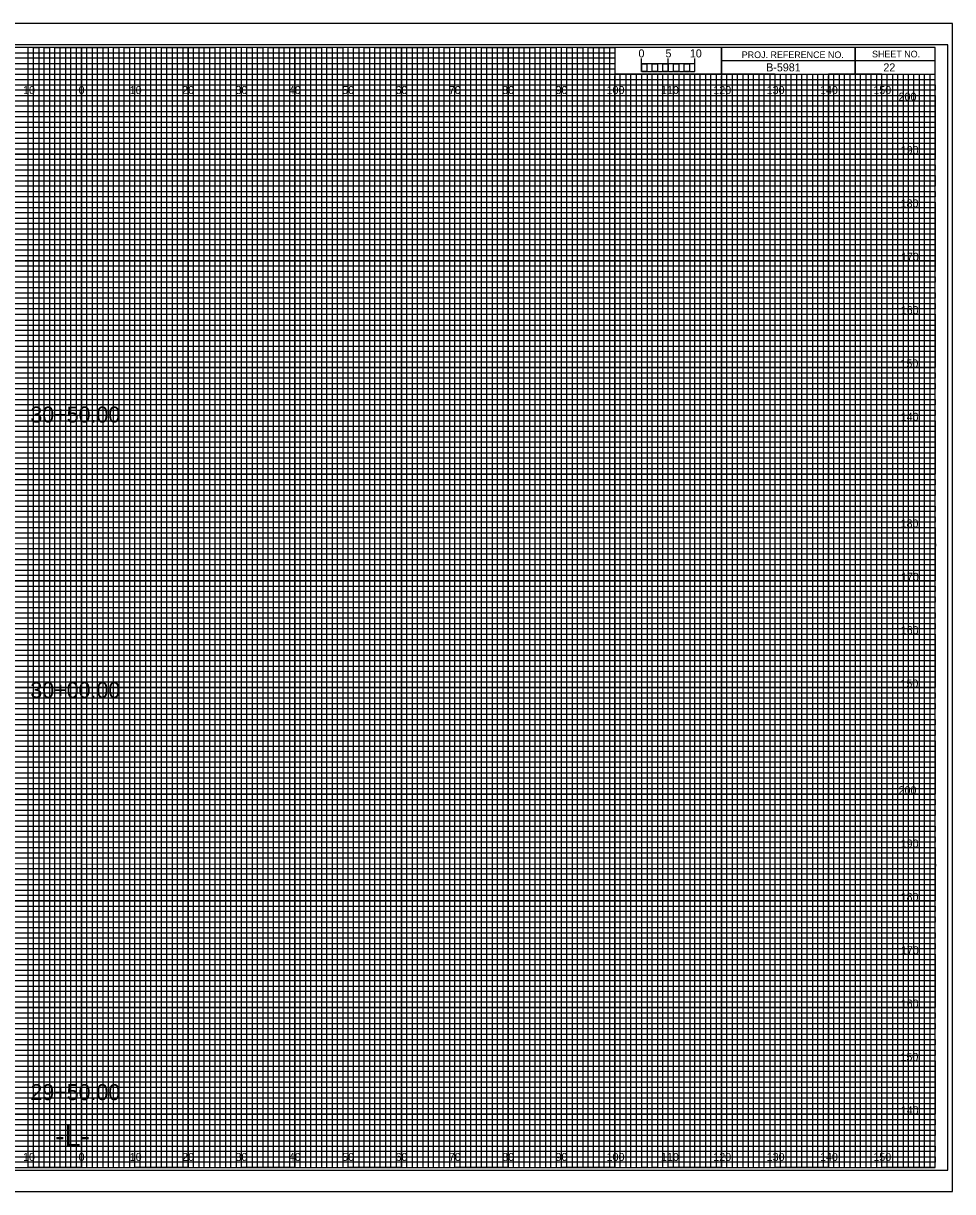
# Model space of a CAD drawing. Extents: x -13 to 323, y -5 to 4174.
# Drawn here: x 149.1 to 323.3, y 3515.5 to 3734.5 of the extents above; entities that cross this region are included whole.
import ezdxf

# ---------------------------------------------------------------- set-up
doc = ezdxf.new("R2010")
doc.units = 0
for name, color, linetype in [('Exist Cross Section Cell', 7, 'Continuous'), ('Exist XS Center Line Elevation Label', 7, 'Continuous'), ('Exist XS Ground Line', 7, 'Continuous'), ('Prop CMT Concrete Structures', 7, 'Continuous'), ('Prop CMT Guardrail Graphics', 7, 'Continuous'), ('Prop CMT Pvmt Course 1', 7, 'Continuous'), ('Prop CMT Pvmt Course 2', 7, 'Continuous'), ('Prop CMT Pvmt Course 3', 7, 'Continuous'), ('Prop CMT Pvmt Surface', 7, 'Continuous'), ('Prop CMT Shld Paved Course 1', 7, 'Continuous'), ('Prop CMT Shld Paved Course 2', 7, 'Continuous'), ('Prop CMT Shld Paved Course 3', 7, 'Continuous'), ('Prop CMT Subgrade Earthwork', 7, 'Continuous'), ('Prop XS Ditch Standard Text', 7, 'Continuous'), ('Prop XS SE Text', 7, 'Continuous'), ('Prop XS Side Slope Text', 7, 'Continuous'), ('Scratch_Level_0', 7, 'Continuous')]:
    doc.layers.add(name, color=color, linetype=linetype)

msp = doc.modelspace()

# ---------------------------------------------------------------- linework, layer by layer
at = {"layer": 'Exist XS Center Line Elevation Label'}
for points in [[(145, 3520), (155, 3520), (155, 3730), (165, 3730), (165, 3520), (175, 3520), (175, 3730), (185, 3730), (185, 3520), (195, 3520), (195, 3730), (205, 3730), (205, 3520), (215, 3520), (215, 3730), (225, 3730), (225, 3520), (235, 3520), (235, 3730), (245, 3730), (245, 3520), (255, 3520), (255, 3730), (259.93, 3730), (260, 3730), (260, 3725), (264.99, 3725), (264.99, 3520), (275, 3520), (275, 3725), (285, 3725), (285, 3520), (295, 3520), (295, 3725), (305, 3725), (305, 3520), (315, 3520), (315, 3725)], [(0, 3725), (275, 3725)], [(0, 3705), (320, 3705), (320, 3715), (0, 3715)], [(0, 3685), (320, 3685), (320, 3695), (0, 3695)], [(0, 3665), (320, 3665), (320, 3675), (0, 3675)], [(0, 3645), (320, 3645), (320, 3655), (0, 3655)], [(0, 3625), (320, 3625), (320, 3635), (0, 3635)], [(0, 3605), (320, 3605), (320, 3615), (0, 3615)], [(0, 3585), (320, 3585), (320, 3595), (0, 3595)], [(0, 3565), (320, 3565), (320, 3575), (0, 3575)], [(0, 3545), (320, 3545), (320, 3555), (0, 3555)], [(0, 3525), (320, 3525), (320, 3535), (0, 3535)]]:
    msp.add_lwpolyline(points, dxfattribs=at)
at = {"layer": 'Exist XS Ground Line'}
for p, q in [((150, 3730), (140, 3730)), ((150, 3520), (150, 3730)), ((170, 3730), (160, 3730)), ((160, 3730), (160, 3520)), ((170, 3520), (170, 3730)), ((190, 3730), (180, 3730)), ((180, 3730), (180, 3520)), ((190, 3520), (190, 3730)), ((210, 3730), (200, 3730)), ((200, 3730), (200, 3520)), ((210, 3520), (210, 3730)), ((230, 3730), (220, 3730)), ((220, 3730), (220, 3520)), ((230, 3520), (230, 3730)), ((250, 3730), (240, 3730)), ((240, 3730), (240, 3520)), ((250, 3520), (250, 3730)), ((260, 3730), (260, 3520)), ((270, 3520), (270, 3725)), ((290, 3725), (280, 3725)), ((280, 3725), (280, 3520)), ((290, 3520), (290, 3725)), ((310, 3725), (300, 3725)), ((300, 3725), (300, 3520)), ((310, 3520), (310, 3725)), ((160, 3520), (150, 3520)), ((180, 3520), (170, 3520)), ((200, 3520), (190, 3520)), ((220, 3520), (210, 3520)), ((240, 3520), (230, 3520)), ((260, 3520), (250, 3520)), ((280, 3520), (270, 3520)), ((300, 3520), (290, 3520)), ((320, 3520), (310, 3520)), ((320, 3520), (320, 3520))]:
    msp.add_line(p, q, dxfattribs=at)
for points in [[(0, 3720), (320, 3720), (320, 3710), (0, 3710)], [(0, 3700), (320, 3700), (320, 3690), (0, 3690)], [(0, 3680), (320, 3680), (320, 3670), (0, 3670)], [(0, 3660), (320, 3660), (320, 3650), (0, 3650)], [(0, 3640), (320, 3640), (320, 3630), (0, 3630)], [(0, 3620), (320, 3620), (320, 3610), (0, 3610)], [(0, 3600), (320, 3600), (320, 3590), (0, 3590)], [(0, 3580), (320, 3580), (320, 3570), (0, 3570)], [(0, 3560), (320, 3560), (320, 3550), (0, 3550)], [(0, 3540), (320, 3540), (320, 3530), (0, 3530)]]:
    msp.add_lwpolyline(points, dxfattribs=at)
at = {"layer": 'Prop CMT Pvmt Course 1'}
for p, q in [((323.3, 3734.5), (-13.4, 3734.5)), ((-13.4, 3515.5), (323.3, 3515.5))]:
    msp.add_line(p, q, dxfattribs=at)
at = {"layer": 'Prop CMT Pvmt Course 2'}
msp.add_lwpolyline([(-13.4, 3515.5), (323.3, 3515.5), (323.3, 3734.5), (-13.4, 3734.5)], close=True, dxfattribs=at)
at = {"layer": 'Prop CMT Pvmt Course 3'}
msp.add_lwpolyline([(-10.8, 3519.5), (322.4, 3519.5), (322.4, 3730.5), (-10.8, 3730.5)], close=True, dxfattribs=at)
at = {"layer": 'Prop CMT Shld Paved Course 1'}
for p, q in [((305, 3730), (305, 3725)), ((305, 3725), (305, 3730)), ((280, 3727.5), (280, 3725)), ((320, 3727.49), (280, 3727.49)), ((280, 3725), (320, 3725))]:
    msp.add_line(p, q, dxfattribs=at)
for points in [[(320, 3730), (0, 3730), (0, 3520), (320, 3520)], [(280, 3730), (260, 3730), (260, 3725.03), (280, 3725.03)], [(320, 3730), (280, 3730), (280, 3725), (320, 3725)]]:
    msp.add_lwpolyline(points, close=True, dxfattribs=at)
at = {"layer": 'Prop CMT Shld Paved Course 2'}
for p, q in [((267, 3725), (266.01, 3725)), ((266.01, 3725), (266.01, 3520)), ((267, 3520), (267, 3725)), ((269, 3725), (268, 3725)), ((268, 3725), (268, 3520)), ((269, 3520), (269, 3725)), ((266.01, 3520), (265, 3520)), ((268, 3520), (267, 3520))]:
    msp.add_line(p, q, dxfattribs=at)
for points in [[(150, 3520), (151, 3520), (151, 3730), (152, 3730), (152, 3520)], [(152, 3520), (153, 3520), (153, 3730), (154, 3730), (154, 3520)], [(155, 3520), (156, 3520), (156, 3730), (157, 3730), (157, 3520)], [(157, 3520), (158, 3520), (158, 3730), (159, 3730), (159, 3520)], [(160, 3520), (161, 3520), (161, 3730), (162, 3730), (162, 3520)], [(162, 3520), (163, 3520), (163, 3730), (164, 3730), (164, 3520)], [(165, 3520), (166, 3520), (166, 3730), (167, 3730), (167, 3520)], [(167, 3520), (168, 3520), (168, 3730), (169, 3730), (169, 3520)], [(170, 3520), (171, 3520), (171, 3730), (172, 3730), (172, 3520)], [(172, 3520), (173, 3520), (173, 3730), (174, 3730), (174, 3520)], [(175, 3520), (176, 3520), (176, 3730), (177, 3730), (177, 3520)], [(177, 3520), (178, 3520), (178, 3730), (179, 3730), (179, 3520)], [(180, 3520), (181, 3520), (181, 3730), (182, 3730), (182, 3520)], [(182, 3520), (183, 3520), (183, 3730), (184, 3730), (184, 3520)], [(185, 3520), (186, 3520), (186, 3730), (187, 3730), (187, 3520)], [(187, 3520), (188, 3520), (188, 3730), (189, 3730), (189, 3520)], [(190, 3520), (191, 3520), (191, 3730), (192, 3730), (192, 3520)], [(192, 3520), (193, 3520), (193, 3730), (194, 3730), (194, 3520)], [(195, 3520), (196, 3520), (196, 3730), (197, 3730), (197, 3520)], [(197, 3520), (198, 3520), (198, 3730), (199, 3730), (199, 3520)], [(200, 3520), (201, 3520), (201, 3730), (202, 3730), (202, 3520)], [(202, 3520), (203, 3520), (203, 3730), (204, 3730), (204, 3520)], [(205, 3520), (206, 3520), (206, 3730), (207, 3730), (207, 3520)], [(207, 3520), (208, 3520), (208, 3730), (209, 3730), (209, 3520)], [(210, 3520), (211, 3520), (211, 3730), (212, 3730), (212, 3520)], [(212, 3520), (213, 3520), (213, 3730), (214, 3730), (214, 3520)], [(215, 3520), (216, 3520), (216, 3730), (217, 3730), (217, 3520)], [(217, 3520), (218, 3520), (218, 3730), (219, 3730), (219, 3520)], [(220, 3520), (221, 3520), (221, 3730), (222, 3730), (222, 3520)], [(222, 3520), (223, 3520), (223, 3730), (224, 3730), (224, 3520)], [(225, 3520), (226, 3520), (226, 3730), (227, 3730), (227, 3520)], [(227, 3520), (228, 3520), (228, 3730), (229, 3730), (229, 3520)], [(230, 3520), (231, 3520), (231, 3730), (232, 3730), (232, 3520)], [(232, 3520), (233, 3520), (233, 3730), (234, 3730), (234, 3520)], [(235, 3520), (236, 3520), (236, 3730), (237, 3730), (237, 3520)], [(237, 3520), (238, 3520), (238, 3730), (239, 3730), (239, 3520)], [(240, 3520), (241, 3520), (241, 3730), (242, 3730), (242, 3520)], [(242, 3520), (243, 3520), (243, 3730), (244, 3730), (244, 3520)], [(245, 3520), (246, 3520), (246, 3730), (247, 3730), (247, 3520)], [(247, 3520), (248, 3520), (248, 3730), (249, 3730), (249, 3520)], [(250, 3520), (251, 3520), (251, 3730), (252, 3730), (252, 3520)], [(252, 3520), (253, 3520), (253, 3730), (254, 3730), (254, 3520)], [(255, 3520), (256, 3520), (256, 3730), (257, 3730), (257, 3520)], [(257, 3520), (258, 3520), (258, 3730), (259, 3730), (259, 3520)], [(260, 3520), (261, 3520), (261, 3725), (262.02, 3725), (262.02, 3520)], [(262, 3520), (263, 3520), (263, 3725), (263.99, 3725), (263.99, 3520)], [(270, 3520), (270.98, 3520), (270.98, 3725), (272, 3725), (272, 3520)], [(272, 3520), (273, 3520), (273, 3725), (274.05, 3725), (274.05, 3520)], [(275, 3520), (276, 3520), (276, 3725), (277, 3725), (277, 3520)], [(277, 3520), (278, 3520), (278, 3725), (279, 3725), (279, 3520)], [(280, 3520), (281, 3520), (281, 3725), (282, 3725), (282, 3520)], [(282, 3520), (283, 3520), (283, 3725), (284, 3725), (284, 3520)], [(285, 3520), (286, 3520), (286, 3725), (287, 3725), (287, 3520)], [(287, 3520), (288, 3520), (288, 3725), (289, 3725), (289, 3520)], [(290, 3520), (291, 3520), (291, 3725), (292, 3725), (292, 3520)], [(292, 3520), (293, 3520), (293, 3725), (294, 3725), (294, 3520)], [(295, 3520), (296, 3520), (296, 3725), (297, 3725), (297, 3520)], [(297, 3520), (298, 3520), (298, 3725), (299, 3725), (299, 3520)], [(300, 3520), (301, 3520), (301, 3725), (302, 3725), (302, 3520)], [(302, 3520), (303, 3520), (303, 3725), (304, 3725), (304, 3520)], [(305, 3520), (306, 3520), (306, 3725), (307, 3725), (307, 3520)], [(307, 3520), (308, 3520), (308, 3725), (309, 3725), (309, 3520)], [(310, 3520), (311, 3520), (311, 3725), (312, 3725), (312, 3520)], [(312, 3520), (313, 3520), (313, 3725), (314, 3725), (314, 3520)], [(315, 3520), (316, 3520), (316, 3725), (317, 3725), (317, 3520)], [(317, 3520), (318, 3520), (318, 3725), (319, 3725), (319, 3520)]]:
    msp.add_lwpolyline(points, dxfattribs=at)
at = {"layer": 'Prop CMT Shld Paved Course 3'}
for p, q in [((265, 3725.49), (265, 3727.9)), ((265, 3726.9), (265, 3727.9)), ((270, 3725.49), (270, 3727.9)), ((275, 3725.49), (275, 3727.9)), ((275, 3726.9), (275, 3727.9))]:
    msp.add_line(p, q, dxfattribs=at)
for points in [[(275, 3726.9), (265, 3726.9), (265, 3725.49), (275, 3725.49)], [(265, 3726.9), (266, 3726.9), (266, 3725.49), (265, 3725.49)], [(267, 3726.9), (268, 3726.9), (268, 3725.49), (267, 3725.49)], [(269, 3726.9), (270, 3726.9), (270, 3725.49), (269, 3725.49)], [(271, 3726.9), (272, 3726.9), (272, 3725.49), (271, 3725.49)], [(273, 3726.9), (274, 3726.9), (274, 3725.49), (273, 3725.49)]]:
    msp.add_lwpolyline(points, close=True, dxfattribs=at)
at = {"layer": 'Prop CMT Subgrade Earthwork'}
for p, q in [((150, 3520), (150, 3730)), ((160, 3520), (160, 3730)), ((170, 3520), (170, 3730)), ((180, 3520), (180, 3730)), ((190, 3520), (190, 3730)), ((200, 3520), (200, 3730)), ((210, 3520), (210, 3730)), ((220, 3520), (220, 3730)), ((230, 3520), (230, 3730)), ((240, 3520), (240, 3730)), ((250, 3520), (250, 3730)), ((260, 3520), (260, 3724.69)), ((270, 3520), (270, 3724.69)), ((280, 3520), (280, 3724.69)), ((290, 3520), (290, 3724.69)), ((300, 3520), (300, 3724.69)), ((310, 3520), (310, 3724.69)), ((0, 3720), (320, 3720)), ((0, 3710), (320, 3710)), ((0, 3700), (320, 3700)), ((0, 3690), (320, 3690)), ((0, 3680), (320, 3680)), ((0, 3670), (320, 3670)), ((0, 3660), (320, 3660)), ((0, 3650), (320, 3650)), ((0, 3640), (320, 3640)), ((0, 3630), (320, 3630)), ((0, 3620), (320, 3620)), ((0, 3610), (320, 3610)), ((0, 3600), (320, 3600)), ((0, 3590), (320, 3590)), ((0, 3580), (320, 3580)), ((0, 3570), (320, 3570)), ((0, 3560), (320, 3560)), ((0, 3550), (320, 3550)), ((0, 3540), (320, 3540)), ((0, 3530), (320, 3530))]:
    msp.add_line(p, q, dxfattribs=at)
at = {"layer": 'Scratch_Level_0'}
for p, q in [((0, 3729), (260, 3729)), ((260, 3727.98), (0, 3727.98)), ((260, 3729), (260, 3727.98)), ((0, 3727), (260, 3727)), ((260, 3725.89), (0, 3725.89)), ((260, 3727), (260, 3725.89)), ((0, 3724), (320, 3724))]:
    msp.add_line(p, q, dxfattribs=at)
for points in [[(0, 3723), (270, 3723), (320, 3723), (320, 3722), (0, 3722)], [(0, 3721), (320, 3721), (320, 3719), (0, 3719)], [(0, 3718), (320, 3718), (320, 3717), (0, 3716.98)], [(0, 3716), (320, 3716), (320, 3714), (0, 3714)], [(0, 3713), (320, 3713), (320, 3712), (0, 3712)], [(0, 3711), (320, 3711), (320, 3709), (0, 3709)], [(0, 3708), (320, 3708), (320, 3707), (0, 3707)], [(0, 3706), (320, 3706), (320, 3704), (0, 3704)], [(0, 3703), (320, 3703), (320, 3702), (0, 3702)], [(0, 3701), (320, 3701), (320, 3699), (0, 3699)], [(0, 3698), (320, 3698), (320, 3697), (0, 3697)], [(0, 3696), (320, 3696), (320, 3693.95), (320, 3693), (320, 3692), (0, 3692)], [(0, 3694), (320, 3694), (320, 3693), (0, 3693)], [(0, 3691), (320, 3691), (320, 3689), (0, 3689.03)], [(0, 3689.03), (320, 3689), (320, 3688), (0, 3688)], [(0, 3687), (320, 3687), (320, 3686), (0, 3686)], [(0, 3684), (320, 3684), (320, 3683), (0, 3683)], [(0, 3682), (320, 3682), (320, 3681), (0, 3681)], [(-0.07, 3678.89), (320, 3678.89), (320, 3677.88), (-0.07, 3677.88)], [(0, 3677), (320, 3677), (320, 3676), (0, 3676)], [(0, 3674), (320, 3674), (320, 3673), (0, 3673)], [(0, 3672), (320, 3672), (320, 3671), (0, 3671)], [(0, 3669), (320, 3669), (320, 3668), (0, 3668)], [(0, 3667), (320, 3667), (320, 3666), (0, 3666)], [(0, 3664), (320, 3664), (320, 3663), (0, 3663)], [(0, 3662), (320, 3662), (320, 3661), (0, 3661)], [(0, 3659), (320, 3659), (319.99, 3657.98), (0, 3658)], [(0, 3657), (320, 3657), (320, 3656), (0, 3656)], [(0, 3654), (320, 3654), (320, 3653), (0, 3653)], [(0, 3652), (320, 3652), (320, 3651), (0, 3651)], [(0, 3649), (320, 3649), (320, 3648), (0, 3648)], [(0, 3647), (320, 3647), (320, 3646), (0, 3646)], [(0, 3644), (320, 3644), (320, 3643), (0, 3643)], [(0, 3642), (320, 3642), (320, 3641), (0, 3641)], [(0, 3639), (320, 3639), (320, 3638), (0, 3638)], [(0, 3636.99), (320.07, 3636.91), (320, 3636), (0, 3636)], [(0, 3634), (320, 3634), (320, 3633), (0, 3633)], [(0, 3632), (320, 3632), (320, 3631), (0, 3631)], [(0, 3629), (320, 3629), (320, 3628), (0, 3628)], [(0, 3627), (320, 3627), (320, 3626), (0, 3626)], [(0, 3624), (320, 3624), (320, 3623), (0, 3623)], [(0, 3622), (320, 3622), (320, 3621), (0, 3621)], [(0, 3619), (320, 3619), (320, 3618), (0, 3618)], [(0, 3617), (320, 3617), (320, 3616), (0, 3616)], [(0, 3614), (320, 3614), (320, 3613), (0, 3613)], [(0, 3612), (320, 3612), (320, 3611), (0, 3611)], [(0, 3609), (320, 3609), (320, 3608), (0, 3608)], [(0, 3607), (320, 3607), (320, 3606), (0, 3606)], [(0, 3604), (320, 3604), (320, 3603), (0, 3603)], [(0, 3602), (320, 3602), (320, 3601), (0, 3601)], [(0, 3599), (320, 3599), (319.99, 3597.98), (0, 3598)], [(0, 3597), (320, 3597), (320, 3596), (0, 3596)], [(0, 3594), (320, 3594), (320, 3593), (0, 3593)], [(0, 3592), (320, 3592), (320, 3591), (0, 3591)], [(0, 3589), (320, 3589), (320, 3588), (0, 3588)], [(0, 3587), (320, 3587), (320, 3586), (0, 3586)], [(0, 3584), (320, 3584), (320, 3583), (0, 3583)], [(0, 3582), (320, 3582), (320, 3581), (0, 3581)], [(0, 3579), (320, 3579), (320, 3578), (0, 3578)], [(0, 3576.99), (320.07, 3576.91), (320, 3576), (0, 3576)], [(0, 3574), (320, 3574), (320, 3573), (0, 3573)], [(0, 3572), (320, 3572), (320, 3571), (0, 3571)], [(0, 3569), (320, 3569), (320, 3568), (0, 3568)], [(0, 3567), (320, 3567), (320, 3566), (0, 3566)], [(0, 3564), (320, 3564), (320, 3563), (0, 3563)], [(0, 3562), (320, 3562), (320, 3561), (0, 3561)], [(0, 3559), (320, 3559), (320, 3558), (0, 3558)], [(0, 3557), (320, 3557), (320, 3556), (0, 3556)], [(0, 3554), (320, 3554), (320, 3553), (0, 3553)], [(0, 3552), (320, 3552), (320, 3551), (0, 3551)], [(0, 3549), (320, 3549), (320, 3548), (0, 3548)], [(0, 3547), (320, 3547), (320, 3546), (0, 3546)], [(0, 3544), (320, 3544), (320, 3543), (0, 3543)], [(0, 3542), (320, 3542), (320, 3541), (0, 3541)], [(0, 3539), (320, 3539), (320, 3538), (0, 3538)], [(0, 3537), (320, 3537), (320, 3536), (0, 3536)], [(0, 3534), (320, 3534), (320, 3533), (0, 3533)], [(0, 3532), (320, 3532), (320, 3531), (0, 3531)], [(0, 3529), (320, 3529), (320, 3528), (0, 3528)], [(0, 3527), (320, 3527), (320, 3526), (0, 3526)], [(0, 3524), (320, 3524), (320, 3523), (0, 3523)], [(0, 3522), (320, 3522), (320, 3521), (0, 3521)]]:
    msp.add_lwpolyline(points, dxfattribs=at)

# ---------------------------------------------------------------- texts
at = {"layer": 'Exist Cross Section Cell'}
for s, p in [('10', (149.04, 3721.25)), ('0', (159.45, 3721.25)), ('0', (159.45, 3721.25)), ('10', (169.04, 3721.25)), ('20', (178.86, 3721.25)), ('30', (188.86, 3721.25)), ('40', (198.86, 3721.25)), ('50', (208.86, 3721.25)), ('60', (218.86, 3721.25)), ('70', (228.86, 3721.25)), ('80', (238.86, 3721.25)), ('90', (248.86, 3721.25)), ('100', (258.44, 3721.25)), ('110', (268.62, 3721.25)), ('120', (278.44, 3721.25)), ('130', (288.44, 3721.25)), ('140', (298.44, 3721.25)), ('150', (308.44, 3721.25)), ('10', (149.04, 3521.25)), ('0', (159.45, 3521.25)), ('0', (159.45, 3521.25)), ('10', (169.04, 3521.25)), ('20', (178.86, 3521.25)), ('30', (188.86, 3521.25)), ('40', (198.86, 3521.25)), ('50', (208.86, 3521.25)), ('60', (218.86, 3521.25)), ('70', (228.86, 3521.25)), ('80', (238.86, 3521.25)), ('90', (248.86, 3521.25)), ('100', (258.44, 3521.25)), ('110', (268.62, 3521.25)), ('120', (278.44, 3521.25)), ('130', (288.44, 3521.25)), ('140', (298.44, 3521.25)), ('150', (308.44, 3521.25))]:
    msp.add_text(s, height=1.5, dxfattribs=at).set_placement(p)
at = {"layer": 'Prop CMT Concrete Structures'}
for s, p in [('30+50.00', (150.41, 3659.67)), ('30+00.00', (150.41, 3608.03)), ('29+50.00', (150.41, 3532.65))]:
    msp.add_text(s, height=3, dxfattribs=at).set_placement(p)
at = {"layer": 'Prop CMT Guardrail Graphics'}
for s, p in [('200', (313.17, 3720)), ('190', (313.57, 3710)), ('180', (313.55, 3700)), ('170', (313.61, 3690)), ('160', (313.57, 3680)), ('150', (313.52, 3670)), ('140', (313.57, 3660)), ('180', (313.55, 3640)), ('170', (313.61, 3630)), ('160', (313.57, 3620)), ('150', (313.52, 3610)), ('200', (313.17, 3590)), ('190', (313.57, 3580)), ('180', (313.55, 3570)), ('170', (313.61, 3560)), ('160', (313.57, 3550)), ('150', (313.52, 3540)), ('140', (313.57, 3530))]:
    msp.add_text(s, height=1.5, dxfattribs=at).set_placement(p)
at = {"layer": 'Prop CMT Pvmt Surface'}
for s, p in [('5', (269.47, 3728.12)), ('10', (274.04, 3728.12))]:
    msp.add_text(s, height=1.5, dxfattribs=at).set_placement(p)
at = {"layer": 'Prop CMT Shld Paved Course 1'}
for s, p in [('PROJ. REFERENCE NO.', (283.77, 3727.99)), ('SHEET NO.', (308.19, 3728.12))]:
    msp.add_text(s, height=1.25, dxfattribs=at).set_placement(p)
at = {"layer": 'Prop CMT Shld Paved Course 3'}
msp.add_text('0', height=1.5, dxfattribs=at).set_placement((264.41, 3728.12))
at = {"layer": 'Prop XS Ditch Standard Text'}
msp.add_text('-L-', height=4, dxfattribs=at).set_placement((155.06, 3524))
at = {"layer": 'Prop XS SE Text'}
msp.add_text(' B-5981', height=1.5, dxfattribs=at).set_placement((287.79, 3725.5))
at = {"layer": 'Prop XS Side Slope Text'}
msp.add_text('22', height=1.5, dxfattribs=at).set_placement((310.32, 3725.5))

doc.saveas('drawing.dxf')
